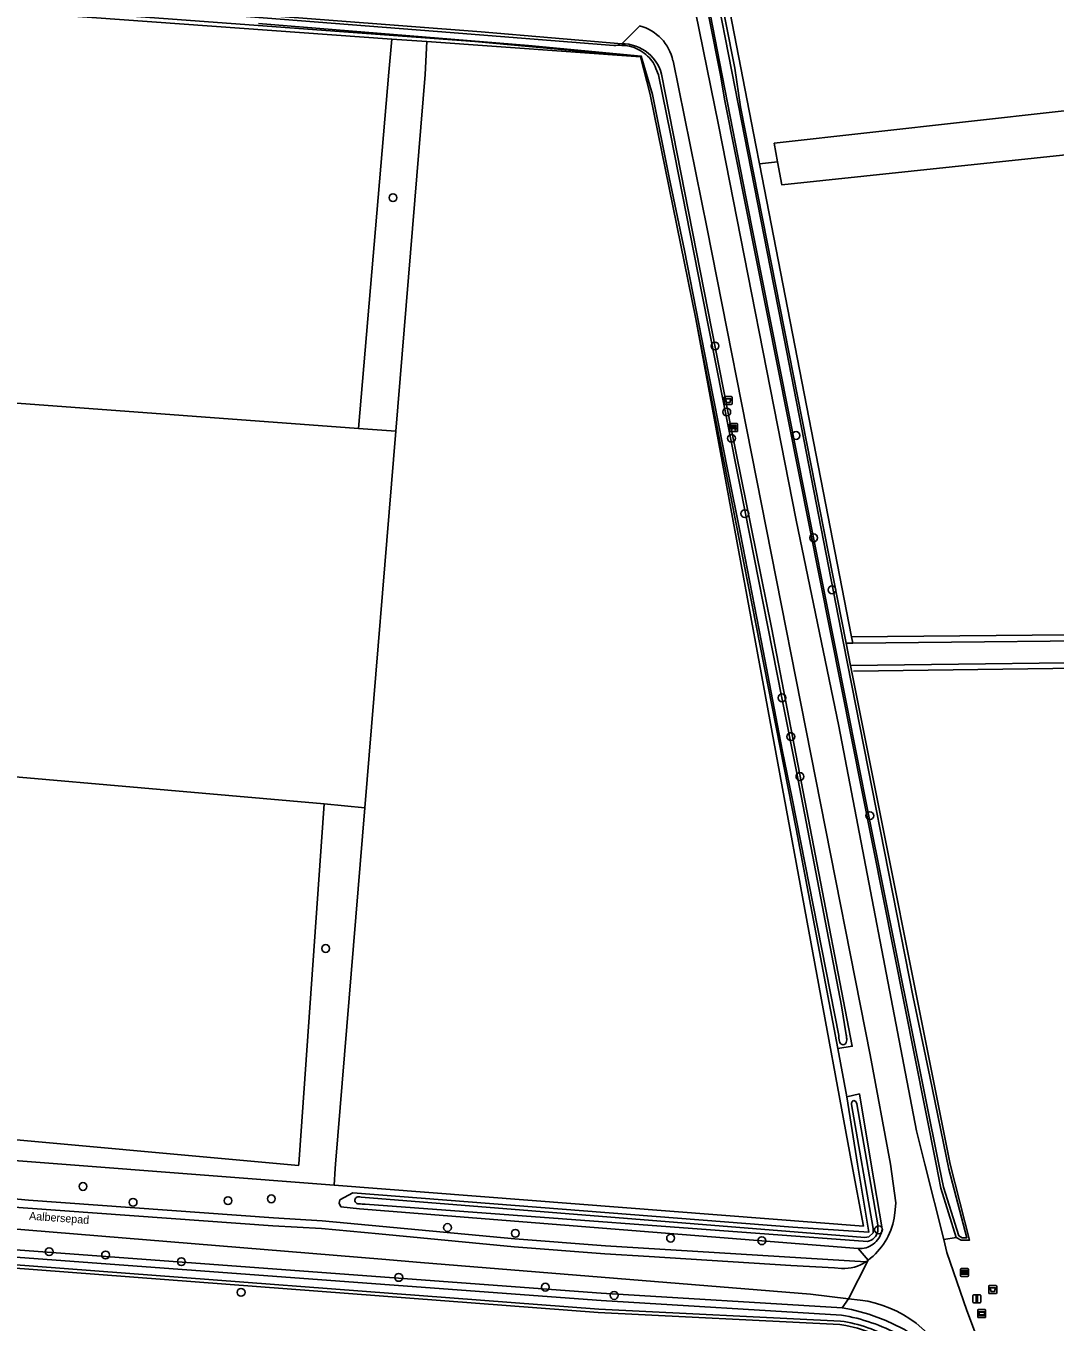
# Model space of a CAD drawing. Extents: x 162722 to 165099, y 384721 to 386283.
# Drawn here: x 164029.1 to 164157.6, y 385230.3 to 385392.2 of the extents above; entities that cross this region are included whole.
import ezdxf

# ---------------------------------------------------------------- set-up
doc = ezdxf.new("R2010")
doc.units = 0
for name, color, linetype in [('IMGEO_Afsluitpaal', 7, 'Continuous'), ('IMGEO_Afvalbak', 7, 'Continuous'), ('IMGEO_Bank', 7, 'Continuous'), ('IMGEO_Boom', 7, 'Continuous'), ('IMGEO_Gemengd_bos', 7, 'Continuous'), ('IMGEO_Grasland_agrarisch', 7, 'Continuous'), ('IMGEO_Grasland_overig', 7, 'Continuous'), ('IMGEO_Groenvoorziening', 7, 'Continuous'), ('IMGEO_Hek', 7, 'Continuous'), ('IMGEO_Loofbos', 7, 'Continuous'), ('IMGEO_Openbare_ruimte_label', 7, 'Continuous'), ('IMGEO_Rijbaan_lokaal_halfverhard', 7, 'Continuous'), ('IMGEO_Straatnaambord', 7, 'Continuous'), ('IMGEO_Voetpad_halfverhard', 7, 'Continuous'), ('IMGEO_Waterloop', 7, 'Continuous'), ('IMGEO_Wegwijzer', 7, 'Continuous')]:
    doc.layers.add(name, color=color, linetype=linetype)

msp = doc.modelspace()

# ---------------------------------------------------------------- linework, layer by layer
at = {"layer": 'IMGEO_Afsluitpaal'}
for p, q in [((164147.34, 385232.78), (164147.34, 385233.58)), ((164147.34, 385233.58), (164147.34, 385232.78)), ((164147.44, 385233.68), (164148.23, 385233.68)), ((164148.23, 385233.68), (164147.44, 385233.68)), ((164148.23, 385232.68), (164147.44, 385232.68)), ((164147.44, 385232.68), (164148.23, 385232.68)), ((164148.33, 385233.58), (164148.33, 385232.78)), ((164148.33, 385232.78), (164148.33, 385233.58))]:
    msp.add_line(p, q, dxfattribs=at)
msp.add_lwpolyline([(164147.76, 385233.56), (164147.91, 385233.56), (164147.91, 385232.81), (164147.76, 385232.81), (164147.76, 385233.56)], dxfattribs=at)
for centre, start, end in [((164147.44, 385233.58), 90, 180), ((164147.44, 385233.58), 90, 180), ((164147.44, 385232.78), 180, 270), ((164147.44, 385232.78), 180, 270), ((164148.23, 385233.58), 0, 90), ((164148.23, 385233.58), 360, 90), ((164148.23, 385232.78), 270, 0), ((164148.23, 385232.78), 270, 0)]:
    msp.add_arc(centre, 0.1, start, end, dxfattribs=at)
at = {"layer": 'IMGEO_Afvalbak'}
for p, q in [((164116.28, 385345.01), (164116.28, 385345.81)), ((164116.28, 385345.81), (164116.28, 385345.01)), ((164116.38, 385345.91), (164117.17, 385345.91)), ((164117.17, 385345.91), (164116.38, 385345.91)), ((164117.27, 385345.81), (164117.27, 385345.01)), ((164117.27, 385345.01), (164117.27, 385345.81)), ((164117.17, 385344.91), (164116.38, 385344.91)), ((164116.38, 385344.91), (164117.17, 385344.91)), ((164149.31, 385233.94), (164149.31, 385234.74)), ((164149.31, 385234.74), (164149.31, 385233.94)), ((164149.41, 385234.84), (164150.2, 385234.84)), ((164150.2, 385234.84), (164149.41, 385234.84)), ((164150.3, 385234.74), (164150.3, 385233.94)), ((164150.3, 385233.94), (164150.3, 385234.74)), ((164150.2, 385233.84), (164149.41, 385233.84)), ((164149.41, 385233.84), (164150.2, 385233.84))]:
    msp.add_line(p, q, dxfattribs=at)
for points in [[(164116.42, 385345.63), (164117.12, 385345.63), (164116.97, 385345.15), (164116.57, 385345.15), (164116.42, 385345.63)], [(164149.45, 385234.55), (164150.16, 385234.55), (164150.01, 385234.08), (164149.6, 385234.08), (164149.45, 385234.55)]]:
    msp.add_lwpolyline(points, dxfattribs=at)
for centre, start, end in [((164116.38, 385345.81), 90, 180), ((164116.38, 385345.81), 90, 180), ((164117.17, 385345.81), 0, 90), ((164117.17, 385345.81), 360, 90), ((164116.38, 385345.01), 180, 270), ((164116.38, 385345.01), 180, 270), ((164117.17, 385345.01), 270, 0), ((164117.17, 385345.01), 270, 0), ((164149.41, 385234.74), 90, 180), ((164149.41, 385234.74), 90, 180), ((164150.2, 385234.74), 0, 90), ((164150.2, 385234.74), 360, 90), ((164149.41, 385233.94), 180, 270), ((164149.41, 385233.94), 180, 270), ((164150.2, 385233.94), 270, 0), ((164150.2, 385233.94), 270, 0)]:
    msp.add_arc(centre, 0.1, start, end, dxfattribs=at)
at = {"layer": 'IMGEO_Bank'}
for p, q in [((164117.01, 385342.52), (164117.85, 385342.52)), ((164117.85, 385342.52), (164117.01, 385342.52)), ((164116.94, 385341.59), (164116.94, 385342.44)), ((164116.94, 385342.44), (164116.94, 385341.59)), ((164117.86, 385341.52), (164117.02, 385341.52)), ((164117.02, 385341.52), (164117.86, 385341.52)), ((164117.63, 385341.92), (164117.24, 385341.92)), ((164117.25, 385342.03), (164117.25, 385342.13)), ((164117.29, 385342.13), (164117.29, 385342.03)), ((164117.58, 385342.14), (164117.3, 385342.14)), ((164117.3, 385342.02), (164117.58, 385342.02)), ((164117.59, 385342.03), (164117.59, 385342.13)), ((164117.63, 385342.13), (164117.63, 385342.03)), ((164117.94, 385342.45), (164117.94, 385341.6)), ((164117.94, 385341.6), (164117.94, 385342.45))]:
    msp.add_line(p, q, dxfattribs=at)
for points in [[(164117.19, 385341.92), (164117.04, 385341.92), (164117.15, 385342.02), (164117.24, 385342.02)], [(164117.24, 385342.14), (164117.15, 385342.14), (164117.15, 385342.3), (164117.72, 385342.3), (164117.72, 385342.14), (164117.64, 385342.14)], [(164117.24, 385341.91), (164117.24, 385341.7), (164117.19, 385341.7), (164117.19, 385341.91)], [(164117.64, 385342.02), (164117.72, 385342.02), (164117.83, 385341.92), (164117.69, 385341.92)], [(164117.68, 385341.91), (164117.68, 385341.7), (164117.64, 385341.7), (164117.64, 385341.91)]]:
    msp.add_lwpolyline(points, dxfattribs=at)
for centre, radius, start, end in [((164117.02, 385342.44), 0.0779, 92.4484, 184.2845), ((164117.02, 385342.44), 0.0779, 92.4484, 184.2845), ((164117.86, 385342.44), 0.0779, 2.4484, 94.2845), ((164117.86, 385342.44), 0.0779, 2.4484, 94.2845), ((164117.02, 385341.6), 0.0779, 182.4484, 274.2845), ((164117.02, 385341.6), 0.0779, 182.4484, 274.2845), ((164117.19, 385341.91), 0.00671, 2.8957, 87.1043), ((164117.24, 385342.13), 0.00671, 2.8957, 87.1043), ((164117.24, 385342.03), 0.00671, 272.8957, 357.1043), ((164117.24, 385341.91), 0.00671, 92.8957, 177.1043), ((164117.3, 385342.13), 0.00671, 92.8957, 177.1043), ((164117.3, 385342.03), 0.00671, 182.8957, 267.1043), ((164117.58, 385342.13), 0.00671, 2.8957, 87.1043), ((164117.58, 385342.03), 0.00671, 272.8957, 357.1043), ((164117.64, 385342.13), 0.00671, 92.8957, 177.1043), ((164117.64, 385342.03), 0.00671, 182.8957, 267.1043), ((164117.63, 385341.91), 0.00671, 2.8957, 87.1043), ((164117.69, 385341.91), 0.00671, 92.8957, 177.1043), ((164117.86, 385341.6), 0.0779, 272.4484, 4.2845), ((164117.86, 385341.6), 0.0779, 272.4484, 4.2845)]:
    msp.add_arc(centre, radius, start, end, dxfattribs=at)
at = {"layer": 'IMGEO_Boom'}
for centre in [(164074.91, 385370.74), (164115.13, 385352.22), (164116.59, 385343.97), (164117.18, 385340.68), (164125.24, 385341.03), (164118.85, 385331.27), (164127.44, 385328.25), (164129.74, 385321.75), (164123.49, 385308.26), (164124.6, 385303.42), (164125.73, 385298.43), (164134.46, 385293.54), (164066.5, 385276.95), (164036.19, 385247.22), (164042.45, 385245.24), (164054.31, 385245.44), (164059.72, 385245.68), (164081.72, 385242.09), (164135.55, 385241.81), (164090.19, 385241.37), (164109.58, 385240.77), (164120.97, 385240.44), (164031.97, 385239.07), (164039.02, 385238.66), (164048.47, 385237.83), (164075.63, 385235.86), (164055.94, 385233.99), (164093.93, 385234.64), (164102.53, 385233.61)]:
    msp.add_circle(centre, 0.489, dxfattribs=at)
at = {"layer": 'IMGEO_Gemengd_bos'}
msp.add_lwpolyline([(164153.54, 385189.83), (164152.38, 385189.32), (164140.97, 385222.37), (164140.64, 385223.3), (164140.22, 385224.2), (164139.73, 385225.06), (164139.16, 385225.87), (164138.52, 385226.63), (164138.22, 385226.95), (164136.98, 385227.77), (164135.68, 385228.48), (164134.31, 385229.06), (164132.9, 385229.53), (164131.45, 385229.86), (164130.71, 385229.98), (164100.55, 385231.49), (164022.81, 385237.41), (164009.25, 385237.64), (164000, 385238.42), (163921.82, 385245)], dxfattribs=at)
at = {"layer": 'IMGEO_Grasland_agrarisch'}
for points in [[(164112.74, 385355.59), (164107.04, 385383.65), (164105.84, 385388.32)], [(164120.68, 385374.99), (164122.94, 385375.24)]]:
    msp.add_lwpolyline(points, dxfattribs=at)
at = {"layer": 'IMGEO_Grasland_overig'}
for points in [[(164093.31, 385497.54), (164095.95, 385485.34), (164100.47, 385462.99), (164101.61, 385458.88), (164101.74, 385458.14), (164103.5, 385448.36), (164107.23, 385429.23), (164115.82, 385386.06), (164116.36, 385382.82), (164142.74, 385250), (164143.33, 385247), (164145.25, 385240.86)], [(164102.81, 385461.1), (164103.46, 385458.26), (164117.58, 385386.93), (164118.32, 385382.1), (164131.49, 385315.1)], [(164104.89, 385456.32), (164120.23, 385377.32), (164120.68, 385374.99)], [(164120.68, 385374.99), (164132.16, 385315.89)], [(164132.16, 385315.89), (164172.82, 385316.27), (164180.17, 385365.7)], [(164132.32, 385315.11), (164132.16, 385315.89)]]:
    msp.add_lwpolyline(points, dxfattribs=at)
at = {"layer": 'IMGEO_Groenvoorziening'}
for points in [[(164131, 385232.07), (164100.92, 385233.9), (164022.69, 385239.69), (164009.22, 385239.9), (164000, 385240.67), (163915.39, 385247.75), (163915.21, 385246.44), (163915.09, 385245.57)], [(164131.8, 385233.18), (164131, 385232.07)], [(164131, 385232.07), (164132.15, 385231.85), (164134.32, 385231.27), (164136.44, 385230.49), (164138.47, 385229.53), (164138.8, 385229.34), (164139.52, 385228.85), (164140.2, 385228.3), (164140.82, 385227.69), (164141.39, 385227.03), (164141.89, 385226.32), (164142.33, 385225.56), (164142.7, 385224.77), (164143, 385223.95), (164143.23, 385223.11), (164145.49, 385216.79), (164152.62, 385195.85), (164153.99, 385192.21), (164154.7, 385190.33), (164153.54, 385189.83)]]:
    msp.add_lwpolyline(points, dxfattribs=at)
at = {"layer": 'IMGEO_Hek'}
for points in [[(164070.61, 385341.89), (164075.26, 385341.59)], [(164132.41, 385311.6), (164172.84, 385312.15)]]:
    msp.add_lwpolyline(points, dxfattribs=at)
at = {"layer": 'IMGEO_Loofbos'}
for points in [[(163899.94, 385406.49), (163945.62, 385403.06), (163971.43, 385400.67), (163995.2, 385398.24), (164000, 385398.06), (164085.92, 385391.45), (164103.5, 385389.96)], [(164105.84, 385388.32), (164085.13, 385390.24), (164000, 385396.58), (163982.95, 385397.31), (163975.24, 385397.92), (163958.6, 385399.87), (163948.37, 385400.74), (163940.26, 385401.16), (163922.3, 385402.69), (163915.42, 385403.08), (163904.36, 385404.18), (163900.82, 385404.42)], [(164074.75, 385390.56), (164014.8, 385394.87), (164000, 385395.93), (163986.38, 385396.95)], [(164103.5, 385389.96), (164105.72, 385392.2)], [(164070.61, 385341.89), (164074.39, 385386.44), (164074.75, 385390.56)], [(164074.75, 385390.56), (164079.15, 385390.24)], [(164075.26, 385341.59), (164078.91, 385386.13), (164079.15, 385390.24)], [(164079.15, 385390.24), (164105.84, 385388.32)], [(164103.5, 385389.96), (164103.91, 385389.95), (164104.35, 385389.9), (164104.79, 385389.81), (164105.22, 385389.68), (164105.64, 385389.51), (164106.04, 385389.31), (164106.42, 385389.07), (164106.78, 385388.8), (164107.11, 385388.49), (164107.42, 385388.16), (164107.69, 385387.81), (164107.93, 385387.43), (164108.14, 385387.03), (164108.3, 385386.61), (164108.44, 385386.18), (164117.15, 385341.91), (164122.2, 385317.06), (164132.26, 385264.74), (164130.48, 385264.46)], [(164122.94, 385375.24), (164122.52, 385377.55), (164182.26, 385384.2), (164182.75, 385384.22)], [(164181.84, 385378.47), (164181.36, 385378.47), (164123.46, 385372.36), (164122.94, 385375.24)], [(164112.74, 385355.59), (164132.23, 385250), (164133.65, 385242.28), (164067.56, 385247.38)], [(164130.48, 385264.46), (164125.25, 385291.91), (164112.74, 385355.59)], [(163974.78, 385302.89), (164000, 385323.52), (164026.82, 385345.17), (164070.61, 385341.89)], [(164075.26, 385341.59), (164070.61, 385341.89)], [(164071.39, 385294.52), (164075.26, 385341.59)], [(164132.05, 385312.31), (164144.49, 385250), (164146.92, 385240.52), (164145.85, 385240.53), (164145.25, 385240.86)], [(164066.33, 385295.02), (164063.14, 385250), (164063.13, 385249.85), (163976.14, 385257.74), (163979.59, 385302.53)], [(163979.59, 385302.53), (164000, 385300.8), (164004.39, 385300.42), (164066.33, 385295.02)], [(164066.33, 385295.02), (164071.39, 385294.52)], [(164071.39, 385294.52), (164067.74, 385250), (164067.7, 385249.46), (164067.56, 385247.38)], [(164131.6, 385258.43), (164130.48, 385264.46)], [(164132.99, 385239.47), (164070.72, 385244.43), (164068.4, 385244.69), (164068.17, 385245.13), (164068.29, 385245.53), (164069.9, 385246.43), (164124.85, 385242.13), (164134.35, 385241.52), (164132.94, 385250), (164131.6, 385258.43)], [(164131.6, 385258.43), (164133.16, 385258.79), (164134.64, 385250), (164136, 385241.91), (164135.96, 385241.68), (164135.9, 385241.43), (164135.81, 385241.2), (164135.7, 385240.97), (164135.58, 385240.75), (164135.43, 385240.54), (164135.27, 385240.35), (164135.08, 385240.18), (164134.89, 385240.02), (164134.68, 385239.88), (164134.46, 385239.75), (164134.23, 385239.65), (164133.99, 385239.57), (164133.75, 385239.51), (164133.5, 385239.47), (164133.24, 385239.46), (164132.99, 385239.47)], [(163896, 385257.12), (163910.06, 385255.42), (163921.3, 385254.48), (163930.5, 385253.6), (163945.64, 385252.44), (163964.71, 385250.98), (163985.76, 385249.38), (164003.34, 385247.86), (164010.32, 385247.54), (164014.82, 385246.89), (164029.39, 385245.49), (164059.97, 385243.29), (164066.08, 385242.94), (164090.14, 385240.67), (164101.43, 385239.79), (164110.27, 385239.27), (164133.98, 385237.82)], [(164067.56, 385247.38), (164033.54, 385250), (164000, 385252.59), (163970.67, 385255.02)], [(164145.25, 385240.86), (164143.69, 385240.59)], [(164134.24, 385238.01), (164132.99, 385239.47)]]:
    msp.add_lwpolyline(points, dxfattribs=at)
at = {"layer": 'IMGEO_Rijbaan_lokaal_halfverhard'}
for points in [[(163916.03, 385253.92), (163921.2, 385253.48), (163930.41, 385252.6), (163945.57, 385251.44), (163959.29, 385250.4), (163964.63, 385249.99), (163986.23, 385248.34), (164003.27, 385246.86), (164010.18, 385246.55), (164014.67, 385245.9), (164023.58, 385244.91), (164029.32, 385244.49), (164059.9, 385242.29), (164066, 385241.95), (164073.14, 385241.32), (164090.05, 385239.68), (164101.38, 385238.79), (164106.9, 385238.49), (164124.61, 385237.33), (164130.03, 385237.06), (164130.93, 385236.98)], [(163915.82, 385251.48), (163930.03, 385250), (163974.96, 385246.02), (163992.8, 385244.6), (164000, 385244.17), (164073.51, 385238.14), (164078.34, 385237.74), (164127.03, 385233.75), (164131.8, 385233.18)], [(164134.24, 385238.01), (164131.8, 385233.18)]]:
    msp.add_lwpolyline(points, dxfattribs=at)
for centre, radius, start, end in [((164131.25, 385241.8), 4.82, 266.2278, 304.5395), ((164131.02, 385242.09), 5.2, 304.773, 308.327)]:
    msp.add_arc(centre, radius, start, end, dxfattribs=at)
at = {"layer": 'IMGEO_Straatnaambord'}
for p, q in [((164147.93, 385230.94), (164147.93, 385231.74)), ((164147.93, 385231.74), (164147.93, 385230.94)), ((164148.03, 385231.84), (164148.82, 385231.84)), ((164148.82, 385231.84), (164148.03, 385231.84)), ((164148.82, 385230.84), (164148.03, 385230.84)), ((164148.03, 385230.84), (164148.82, 385230.84)), ((164148.92, 385231.74), (164148.92, 385230.94)), ((164148.92, 385230.94), (164148.92, 385231.74))]:
    msp.add_line(p, q, dxfattribs=at)
for points in [[(164148.03, 385231.57), (164148.82, 385231.57), (164148.82, 385231.1), (164148.03, 385231.1), (164148.03, 385231.57)], [(164148.1, 385231.5), (164148.1, 385231.17), (164148.76, 385231.17), (164148.76, 385231.5), (164148.1, 385231.5)]]:
    msp.add_lwpolyline(points, dxfattribs=at)
for centre, start, end in [((164148.03, 385231.74), 90, 180), ((164148.03, 385231.74), 90, 180), ((164148.03, 385230.94), 180, 270), ((164148.03, 385230.94), 180, 270), ((164148.82, 385231.74), 0, 90), ((164148.82, 385231.74), 360, 90), ((164148.82, 385230.94), 270, 0), ((164148.82, 385230.94), 270, 0)]:
    msp.add_arc(centre, 0.1, start, end, dxfattribs=at)
at = {"layer": 'IMGEO_Voetpad_halfverhard'}
for points in [[(164143.69, 385240.59), (164141.34, 385250), (164140.3, 385254.17), (164130.58, 385304.72), (164125.24, 385330.47), (164115.55, 385379.85), (164105.07, 385431.45), (164099.85, 385458), (164091.6, 385500), (164089.01, 385513.16), (164083.92, 385538.13)], [(164109.88, 385387.84), (164114.15, 385366.84), (164134.49, 385263.66), (164137.04, 385250), (164137.7, 385245.19), (164137.63, 385244.29), (164137.49, 385243.27)], [(164132.32, 385315.11), (164131.49, 385315.1)], [(164131.49, 385315.1), (164132.05, 385312.31)], [(164173.44, 385315.52), (164132.32, 385315.11)], [(164132.05, 385312.31), (164172.45, 385312.79)], [(164156.55, 385202.26), (164153.27, 385212.59), (164149.17, 385224.84), (164146.56, 385231.72), (164144.09, 385238.99), (164143.69, 385240.59)], [(164131.8, 385233.18), (164133.24, 385233.03)]]:
    msp.add_lwpolyline(points, dxfattribs=at)
for centre, radius, start, end in [((164104.28, 385386.67), 5.71, 11.8255, 75.4857), ((164129.17, 385244.78), 8.46, 306.8928, 349.7257), ((164131.34, 385218.61), 14.55, 22.2135, 82.4747)]:
    msp.add_arc(centre, radius, start, end, dxfattribs=at)
at = {"layer": 'IMGEO_Waterloop'}
for points in [[(164203.91, 385527.59), (164203.76, 385527.54), (164183.7, 385525.45), (164165.73, 385522.88), (164134.83, 385515.43), (164125.12, 385512.33), (164115.92, 385508.85), (164107.85, 385504.98), (164094.97, 385497.53), (164100.52, 385470.39), (164109.96, 385423.74), (164122.49, 385359.73), (164123.14, 385356.36), (164131.16, 385315.07), (164139.89, 385270.85), (164141.95, 385260.94), (164144.34, 385249.4), (164146.58, 385240.82), (164145.98, 385240.8), (164145.56, 385241.05)], [(164145.56, 385241.05), (164143.66, 385247.12), (164143.13, 385249.76), (164134.29, 385293.7), (164127.44, 385328.25), (164118.99, 385370.84), (164116.03, 385386.02), (164101.83, 385459.06), (164100.81, 385463.06), (164093.73, 385497.52)], [(163901.65, 385405.84), (163901.81, 385405.89), (163901.97, 385405.94), (163920.74, 385404.54), (163928.4, 385404.04), (163954.11, 385401.78), (163973.74, 385399.8), (163995.15, 385397.86), (164000.16, 385397.77), (164023.36, 385395.85), (164039.03, 385394.7), (164054.45, 385393.56), (164080.45, 385391.5), (164102.5, 385389.75)], [(164130.67, 385265.35), (164130.63, 385265.53), (164130.6, 385265.73), (164130.57, 385266.08), (164124.74, 385295.68), (164123.53, 385301.75), (164120.94, 385315.23), (164118.31, 385328.69), (164116.73, 385336.59), (164113.83, 385351.34), (164111.33, 385364.15), (164109.41, 385373.27), (164107.33, 385383.65), (164105.92, 385388.44), (164091.82, 385389.76), (164058.13, 385392.49)], [(164107.74, 385386.9), (164108.07, 385386.07), (164109.58, 385378.71), (164113.53, 385358.59), (164117.85, 385336.74), (164118.25, 385334.66), (164123.49, 385308.26), (164125.32, 385299.04), (164130.91, 385269.78), (164131.51, 385266.16), (164131.53, 385266.02)], [(164070.61, 385245.94), (164070.76, 385245.92), (164070.92, 385245.89), (164133.84, 385240.86), (164134.34, 385240.94), (164134.89, 385241.44), (164134.89, 385241.99), (164132.18, 385257.47)], [(164132.18, 385257.47), (164132.17, 385257.62)], [(164132.71, 385257.82), (164132.75, 385257.74), (164132.82, 385257.56), (164135.44, 385242.42), (164135.48, 385241.62)], [(164130.94, 385231.14), (164100.9, 385232.96), (164022.68, 385238.75), (164009.21, 385238.96), (163999.97, 385239.73), (163916.32, 385246.93)], [(163916.39, 385245.87), (163921.9, 385245.41), (164000.08, 385238.83), (164009.31, 385238.05), (164022.87, 385237.82), (164100.62, 385231.9), (164130.8, 385230.39)], [(164134.18, 385240.35), (164071.42, 385245.02)]]:
    msp.add_lwpolyline(points, dxfattribs=at)
for centre, radius, start, end in [((164103.16, 385382.64), 7.14, 79.5773, 95.3292), ((164103.09, 385384.51), 5.34, 50.2516, 75.1721), ((164104.11, 385385.57), 3.87, 20.0866, 51.8009), ((164131.41, 385265.52), 0.763, 192.3941, 215.1048), ((164131.11, 385265.37), 0.437, 221.8643, 289.2614), ((164131.15, 385265.32), 0.374, 286.9548, 340.6483), ((164130.45, 385265.57), 1.12, 339.9729, 358.1704), ((164129.31, 385265.61), 2.26, 358.1912, 10.5339), ((164132.53, 385257.6), 0.355, 118.814, 176.1403), ((164132.49, 385257.69), 0.256, 31.231, 120.8506), ((164070.64, 385245.48), 0.488, 145.5662, 199.6712), ((164070.66, 385245.59), 0.547, 209.8727, 271.9983), ((164070.58, 385245.53), 0.407, 85.5358, 145.9681), ((164071.27, 385250.87), 5.85, 264.1278, 271.3898), ((164133.77, 385242.05), 1.75, 283.534, 345.8857), ((164127.08, 385207.95), 23.51, 61.8204, 80.5618), ((164128.44, 385213.23), 17.33, 59.0227, 82.1567)]:
    msp.add_arc(centre, radius, start, end, dxfattribs=at)
at = {"layer": 'IMGEO_Wegwijzer'}
for p, q in [((164145.8, 385236.08), (164145.8, 385236.88)), ((164145.8, 385236.88), (164145.8, 385236.08)), ((164145.9, 385236.98), (164146.68, 385236.98)), ((164146.68, 385236.98), (164145.9, 385236.98)), ((164146.68, 385235.98), (164145.9, 385235.98)), ((164145.9, 385235.98), (164146.68, 385235.98)), ((164146.78, 385236.88), (164146.78, 385236.08)), ((164146.78, 385236.08), (164146.78, 385236.88))]:
    msp.add_line(p, q, dxfattribs=at)
for points in [[(164145.9, 385236.71), (164146.68, 385236.71), (164146.68, 385236.25), (164145.9, 385236.25), (164145.9, 385236.71)], [(164145.96, 385236.56), (164145.96, 385236.48), (164145.96, 385236.4), (164146.37, 385236.4), (164146.37, 385236.31), (164146.62, 385236.48), (164146.37, 385236.65), (164146.37, 385236.56), (164145.96, 385236.56)]]:
    msp.add_lwpolyline(points, dxfattribs=at)
for centre, start, end in [((164145.9, 385236.88), 90, 180), ((164145.9, 385236.88), 90, 180), ((164145.9, 385236.08), 180, 270), ((164145.9, 385236.08), 180, 270), ((164146.68, 385236.88), 0, 90), ((164146.68, 385236.88), 360, 90), ((164146.68, 385236.08), 270, 0), ((164146.68, 385236.08), 270, 0)]:
    msp.add_arc(centre, 0.1, start, end, dxfattribs=at)

# ---------------------------------------------------------------- texts
at = {"layer": 'IMGEO_Openbare_ruimte_label'}
msp.add_text('Aalbersepad', height=1, rotation=355.9266, dxfattribs=at).set_placement((164029.44, 385243.07))

doc.saveas('drawing.dxf')
